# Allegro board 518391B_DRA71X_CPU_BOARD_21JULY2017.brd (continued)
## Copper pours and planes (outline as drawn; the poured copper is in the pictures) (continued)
N31206880 on TOP: 17.91,141.35 19.18,141.35 20.45,142.62 23.11,142.62 23.18,142.56 26.23,142.56 29.21,139.57 29.21,125.86 26.03,122.68 14.61,122.68 14.61,127.76 14.86,128.02 22.48,128.02 24,129.54 24,132.72 23.49,133.22 20.57,133.22 17.91,135.89
N31207093 on BOTTOM: 17.78,145.16 27.3,145.16 27.43,145.29 27.43,147.83 26.54,148.72 17.78,148.72
N31208551 on TOP: 87.25,124.71 86.23,123.7 86.23,119.25 93.73,119.25 93.73,124.46 93.47,124.71
N31208551 on BOTTOM: 86.87,126.62 90.8,126.62 91.82,125.6 91.82,121.67 89.79,119.63 84.58,119.63 84.45,119.76 84.45,122.94 86.87,125.35
N31223527 on TOP: 90.3,140.21 90.3,138.05 90.04,137.8 86.87,137.8 86.87,136.4 86.61,136.14 86.11,136.14 85.85,136.4 85.85,137.8 83.95,137.8 83.95,141.86 88.01,141.86 88.01,140.21
N31635587 on TOP (solid shape): 6.22,18.03 2.79,18.03 2.79,21.08 6.22,21.08
N31636510 on TOP (solid shape): 6.22,29.46 2.79,29.46 2.79,32.51 6.22,32.51
N31637058 on TOP (solid shape): 6.22,40.89 2.79,40.89 2.79,43.94 6.22,43.94
N31638056 on TOP (solid shape): 6.22,52.32 2.79,52.32 2.79,55.37 6.22,55.37
N31638278 on TOP (solid shape): 6.22,63.75 2.79,63.75 2.79,66.8 6.22,66.8
N31730797 on TOP: 13.72,152.78 13.72,150.75 14.35,150.11 18.03,150.11 18.03,145.03 23.62,145.03 24.51,145.92 24.51,152.4 22.48,154.43 15.37,154.43

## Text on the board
BOTTOM: LOGIC 518392 REV B | PWB 518391 REV B | LAYER 6
Board Geometry/Soldermask Bottom: SMS
Ref Des/Silkscreen Bottom: GND | S/N | A2B EXPANSION | ASSY 518390 REV | FOR EVALUATION ONLY; | NOT FCC APPROVED FOR RESALE | CSI-IN | A | BSLK
User.Comments: TEXAS INSTRUMENTS
Board Geometry/Outline: 7-21-17 | BREAK OFF TAB
TOP: LAYER 1
Ref Des/Assembly Top: CONN.CABLE
Board Geometry/Soldermask Top: SMC
Ref Des/Silkscreen Top: CAM_OEN | CAMERA | VSYS | 16V0 | 1 | CONSOLE | CLASS-D | MIC-2 | MIC-3 | MIC-1 | MIC-4 | MIC-5 | GND | TUNE-1 | TUNE-2 | PMIC_EN | HDMI | J6-DEBUG | COMM | USB-SS | BOOT | USB-HS | DISPLAY | GNSS | WiLINK | A | AUTH | MCU-DEBUG | VBAT | DRA71x LCARD CPU BOARD | TSLK
L2_GND: LAYER 2
LY3: LAYER 3
LY4: LAYER 4
LY5_PWR: LAYER 5
USER_PART_NUM_TOP: TSLKC
USER_PART_NUM_BOTTOM: BSLKC
DISPLAY_BOTTOM: SPS
DISPLAY_TOP: SPC
User.15: ANALOG DEVICES | PLUG-ON CARD
User.16: DATE | DESIGN ENGR | PROJECT ENGR | ENGR MGR | NEXT ASSEMBLY | APPROVED | CHECKED | DRAFTING | ENGR | NONE | 1 OF 1 | 2.  REFER TO STACKUP DRAWING FOR COPPER WEIGHT. | 1.  TOTAL BOARD THICKNESS SHALL BE .062 +/- 10% INCHES. | NOTES: UNLESS OTHERWISE SPECIFIED | 4.  SOLDERMASK ON BOTH SIDES OF THE BOARD SHALL BE S.M.O.B.C., LPI, COLOR GREEN. | 3.  MINIMUM CLEARANCE ON THE BOARD SHALL BE 3.0 MILS. | 5.  PLATED THRU HOLE SIZE TOLERANCES SHALL BE +/- .003 INCH. | 6.  DRC'S MUST BE RUN ON THE GERBERS BEFORE BUILDING BOARDS UNLESS PRIOR | 7.  FINISHED BOARD SHALL BE FREE OF BURRS ON EDGES. | 8.  SURFACE FINISH SHALL BE IMMERSION GOLD. | 9.  IMPEDANCE CONTROL: | AVERAGE COPPER ON THE WALL OF THE | PLATED HOLE SHALL BE PER IPC CLASS 2. | ALL MATERIAL SHALL BE NEMA GRADE FR-4 OR EQUIVALENT. (Tg>=170 DEG. C) | UNPLATED THRU HOLE SIZE TOLERANCES SHALL BE +/- .002 INCH. | MINIMUM TRACE WIDTH ON THE BOARD SHALL BE 3.0 MILS. | APPROVAL IS GIVEN IN WRITING. | REFER TO STACKUP DRAWING FOR IMPEDANCE CONTROL. | A | VIEW | SCALE: NONE | TEXAS INSTRUMENTS | LAYER 1 | LAYER 2 | LAYER 5 | LAYER 6 | A-A
User.17: RICHARDSON,TEXAS 75081 | 1510 N. PLANO RD | (972)931-4100 | SUITE 300 | QC GRAPHICS INC. | DATE | DESIGN ENGR | PROJECT ENGR | ENGR MGR | NEXT ASSEMBLY | APPROVED | CHECKED | DRAFTING | ENGR | 2 OF 2 | TEXAS INSTRUMENTS
User.18: RICHARDSON,TEXAS 75081 | 1510 N. PLANO RD | (972)931-4100 | SUITE 300 | QC GRAPHICS INC. | NONE | FABRICATION DRAWING, | ADAS 15X15MM | TEXAS INSTRUMENTS
User.19: AUSTIN,TEXAS 78756 | 4410 SHOALWOOD | (512)260-5778 | TURNING CONCEPT | INTO REALITY
User.23: ASSEMBLY COMPONENT SIDE
User.24: ASSEMBLY SOLDER SIDE
User.29: 91.0x40.0 | 98.0x40.0 | 118.0x40.0 | FIGURE | SIZE | 8.0 | 10.0 | 12.0 | 13.0 | 25.0 | 28.0 | 32.0 | 35.0 | 39.0 | 40.0 | 41.3 | 43.0 | 48.0 | 51.0 | 55.0 | 58.0 | 63.0 | 91.0 | 93.0 | 100.0 | 125.0 | PLATED | NON-PLATED | DRILL CHART | ALL UNITS ARE IN MILS | QTY | 252 | 103 | 183 | 2883 | 48 | 91 | 43 | 6 | 18 | 1 | 11 | 2 | 4 | 12 | 31 | 10 | 8 | 3 | 16 | 5 | TOL | NOTE
